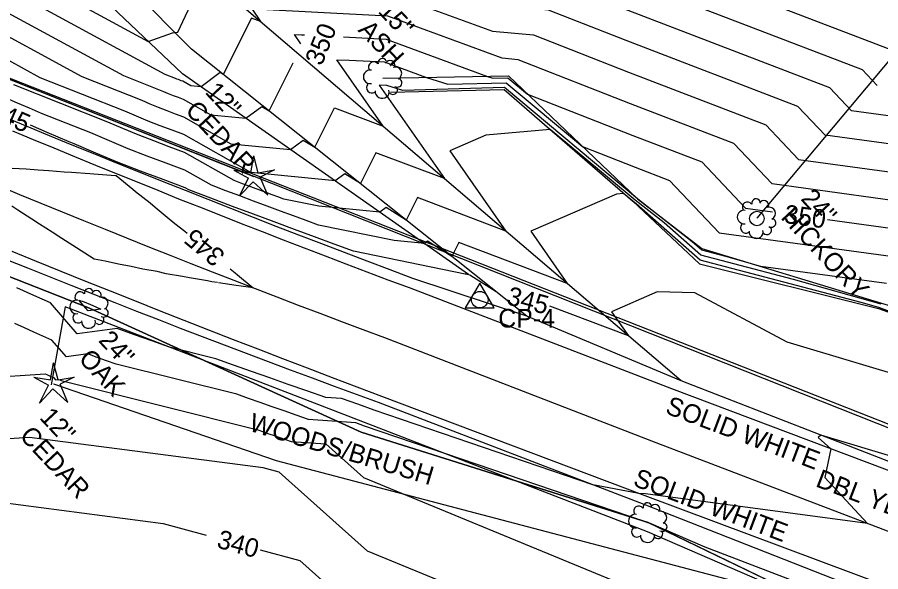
# Model space of a CAD drawing. Extents: x 487096 to 489566, y 221939 to 224454.
# Drawn here: x 487821.4 to 487970.1, y 223738.9 to 223834.5 of the extents above; entities that cross this region are included whole.
import ezdxf

# ---------------------------------------------------------------- set-up
doc = ezdxf.new("R2010")
doc.units = 0
for name, color, linetype in [('SV_BKLN_BKLN', 7, 'Continuous'), ('SV_BKLN_EARTH_TOP', 7, 'Continuous'), ('SV_CTRL_BM', 7, 'Continuous'), ('SV_CTRL_BM_INFO_BOX', 7, 'Continuous'), ('SV_CTRL_CPT', 7, 'Continuous'), ('SV_FENC_FENCES', 7, 'Continuous'), ('SV_MISC_MISC_TOPO', 7, 'Continuous'), ('SV_PIPE_RC_TX', 7, 'Continuous'), ('SV_ROAD_BITRD', 7, 'Continuous'), ('SV_ROAD_GRAVRD', 7, 'Continuous'), ('SV_ROWL_HWYLOC', 7, 'Continuous'), ('SV_SURF_INDEX_CONTOUR', 7, 'Continuous'), ('SV_SURF_INTER_CONTOUR', 7, 'Continuous'), ('SV_TRAF_PVMTL', 7, 'Continuous'), ('SV_TRAF_TRAF_TX', 7, 'Continuous'), ('SV_TREE_TREELN', 7, 'Continuous'), ('SV_TREE_TREEVEG', 7, 'Continuous'), ('SV_TREE_TREEVEG_TX', 7, 'Continuous'), ('SV_UTOH_OVERHEAD_LINES', 7, 'Continuous'), ('SV_WALL_STONE_WALL', 7, 'Continuous')]:
    doc.layers.add(name, color=color, linetype=linetype)

msp = doc.modelspace()

# ---------------------------------------------------------------- linework, layer by layer
at = {"layer": 'SV_BKLN_BKLN'}
msp.add_lwpolyline([(487885.7, 223821.61), (487905.24, 223822.04), (487927.4, 223802.77), (487938.91, 223792), (487969.73, 223784.31), (487995.3, 223775.15), (488005.95, 223768.55)], dxfattribs=at)
at = {"layer": 'SV_BKLN_EARTH_TOP'}
msp.add_lwpolyline([(487899.13, 223790.17), (487849.86, 223824.73), (487785.15, 223886.13)], dxfattribs=at)
at = {"layer": 'SV_CTRL_BM'}
msp.add_line((487948.79, 223799.81), (487948.79, 223799.81), dxfattribs=at)
msp.add_circle((487948.79, 223799.81), 1.25, dxfattribs=at)
at = {"layer": 'SV_CTRL_BM_INFO_BOX'}
msp.add_line((488027.75, 223894.06), (487948.76, 223799.86), dxfattribs=at)
at = {"layer": 'SV_CTRL_CPT'}
for p, q in [((487901.05, 223788.69), (487898.57, 223784.39)), ((487903.54, 223784.39), (487901.05, 223788.69)), ((487901.05, 223785.82), (487901.05, 223785.82)), ((487898.57, 223784.39), (487903.54, 223784.39))]:
    msp.add_line(p, q, dxfattribs=at)
msp.add_circle((487901.05, 223785.82), 1.43, dxfattribs=at)
at = {"layer": 'SV_FENC_FENCES'}
for points in [[(487756.92, 223854.03), (487819.74, 223823.93), (487862.12, 223807.03)], [(488168.14, 223658.69), (488156.25, 223662.12), (488127.21, 223671.39), (488093.65, 223683.37), (488020.23, 223704.76), (487973.09, 223726.63), (487930.05, 223747.42), (487880.61, 223763.01), (487833.81, 223784.33), (487750.08, 223817.31)]]:
    msp.add_lwpolyline(points, dxfattribs=at)
at = {"layer": 'SV_MISC_MISC_TOPO'}
for p, q in [((487901.03, 223785.78), (487901.03, 223785.78)), ((487901.07, 223785.81), (487901.07, 223785.81))]:
    msp.add_line(p, q, dxfattribs=at)
at = {"layer": 'SV_ROAD_BITRD'}
for points in [[(487991.62, 223750.14), (487935.77, 223771.81), (487909.17, 223782.99), (487889.55, 223789.46), (487885.61, 223790.94), (487881.68, 223792.43), (487877.76, 223793.93), (487873.83, 223795.43), (487869.91, 223796.94), (487865.99, 223798.46), (487862.08, 223799.99), (487858.16, 223801.52), (487854.25, 223803.06), (487850.35, 223804.61), (487846.44, 223806.17), (487842.54, 223807.73), (487838.64, 223809.3), (487834.75, 223810.88), (487830.86, 223812.47), (487826.97, 223814.06), (487823.08, 223815.66), (487819.2, 223817.27)], [(487982.7, 223729.58), (487929.37, 223750.5), (487883.63, 223768.08), (487879.84, 223769.47), (487876.04, 223770.87), (487872.25, 223772.28), (487868.46, 223773.7), (487864.67, 223775.12), (487860.88, 223776.55), (487857.1, 223777.99), (487853.32, 223779.43), (487849.54, 223780.88), (487845.77, 223782.34), (487842, 223783.81), (487838.23, 223785.28), (487834.47, 223786.77), (487830.7, 223788.26), (487826.94, 223789.75), (487823.19, 223791.26), (487819.44, 223792.77)]]:
    msp.add_lwpolyline(points, dxfattribs=at)
at = {"layer": 'SV_ROAD_GRAVRD'}
for points in [[(487935.77, 223771.81), (487858.55, 223837.83), (487796.63, 223896.51)], [(487909.17, 223782.99), (487851.39, 223829), (487789.82, 223890.99)]]:
    msp.add_lwpolyline(points, dxfattribs=at)
at = {"layer": 'SV_ROWL_HWYLOC'}
for points in [[(487756.92, 223854.03), (487819.74, 223823.93), (487982.51, 223759.36), (488009.69, 223754.74), (488041.14, 223750.63), (488071.96, 223735.45), (488100.92, 223722.74), (488124.66, 223715.6), (488155.68, 223709.25), (488178.9, 223706.07), (488296.16, 223658.56), (488379.4, 223617.17), (488410.15, 223595.68), (488443.8, 223549.21), (488472.24, 223469.86), (488477.06, 223418.16), (488475.62, 223352.08), (488474.08, 223317.48), (488463.17, 223231.25), (488461.58, 223189.46)], [(487750.08, 223817.31), (487833.81, 223784.33), (487880.61, 223763.01), (487930.05, 223747.42), (487951.57, 223737.03), (487996.66, 223715.69), (488020.23, 223704.76), (488056.94, 223694.06), (488093.65, 223683.37), (488127.21, 223671.39), (488156.25, 223662.12), (488168.14, 223658.69), (488264.6, 223621.9)]]:
    msp.add_lwpolyline(points, dxfattribs=at)
at = {"layer": 'SV_SURF_INDEX_CONTOUR'}
for points in [[(487888.61, 223849.63), (487898.24, 223846.09), (487918.12, 223844.3), (487925.47, 223841.41), (487966.91, 223825.5), (487969.53, 223822.73)], [(487802.49, 223843.56), (487810.68, 223840.22), (487839.71, 223824.46), (487845.74, 223822.07), (487846.58, 223821.71), (487847.41, 223821.36), (487848.27, 223821.03), (487849.12, 223820.71), (487849.97, 223820.4), (487854.74, 223817.68), (487860.74, 223817.09), (487863.51, 223819.14), (487864.76, 223818.36), (487868.89, 223826.63), (487868.91, 223826.62)], [(487870.24, 223829.93), (487869.13, 223831.51), (487870.37, 223831.49), (487870.85, 223831.46)], [(487877.61, 223831.11), (487884.92, 223830.72), (487902.37, 223824.31), (487903.31, 223824.01), (487905.9, 223824.08), (487909.28, 223821.25), (487927.44, 223814.12), (487939.28, 223809.57), (487946.85, 223801.57), (487951.46, 223800.94)], [(487903.86, 223787.18), (487899.33, 223790.03), (487898.86, 223790.15), (487898.72, 223790.19), (487898.57, 223790.24), (487879.32, 223794.2), (487876, 223795.4), (487872.61, 223796.64), (487869.17, 223797.91), (487865.66, 223799.21), (487862.08, 223800.54), (487858.44, 223801.9), (487854.72, 223803.3), (487850.94, 223804.73), (487850.33, 223805.07), (487846.51, 223806.51), (487842.64, 223807.97), (487838.75, 223809.45), (487834.95, 223811.06), (487831.18, 223812.67), (487830.33, 223813.01), (487826.55, 223814.63), (487823.67, 223815.87)], [(487820.51, 223808.51), (487822.95, 223808.35), (487825.02, 223808.19), (487826.86, 223808.07), (487829.48, 223807.87), (487830.75, 223807.79), (487833.91, 223807.54), (487834.6, 223807.5), (487838.29, 223807.21), (487838.43, 223807.2), (487841.29, 223804.89), (487841.78, 223804.49), (487844.26, 223802.49), (487845.15, 223801.74), (487847.24, 223800.06), (487848.55, 223798.97), (487850.24, 223797.61), (487850.64, 223797.28)], [(487855.91, 223788.77), (487854.92, 223788.92), (487854.16, 223789.08), (487851.04, 223789.58), (487849.87, 223789.83), (487847.06, 223790.3), (487845.49, 223790.65), (487843, 223791.09), (487841.04, 223791.54), (487838.86, 223791.93), (487836.52, 223792.48), (487834.65, 223792.83), (487833.05, 223793.84), (487830.99, 223795.18), (487829.1, 223796.38), (487827.4, 223797.47), (487825.24, 223798.84), (487823.9, 223799.71), (487821.48, 223801.25), (487820.47, 223801.91)], [(487960.97, 223799.64), (487973.47, 223797.92), (487993.5, 223788.25), (488003.67, 223781.54), (488008.98, 223772.72), (488010.27, 223767.56), (488011.98, 223766.57), (488014.18, 223764.36), (488018.27, 223753.62), (488024.42, 223749.97)], [(487858.04, 223791.16), (487858.91, 223790.43), (487859.31, 223790.11), (487862.01, 223787.86), (487858.72, 223788.32), (487858.36, 223788.4), (487856.04, 223788.75)], [(487985.01, 223766), (487976.08, 223771.92), (487953.99, 223778.52), (487938.13, 223786.98), (487931.62, 223787.16), (487923.76, 223783.75), (487926.67, 223779.59), (487913.14, 223784.71)], [(487771.75, 223766.41), (487802.26, 223752.04), (487803.55, 223751.39), (487804.83, 223750.74), (487806.1, 223750.11), (487818.48, 223750.92), (487846.53, 223747.27), (487853.95, 223745.24)], [(487863.21, 223742.72), (487870.05, 223740.85), (487882.45, 223729.81), (487911.79, 223717.73), (487942.75, 223718.2)]]:
    msp.add_lwpolyline(points, dxfattribs=at)
msp.add_lwpolyline([(487832.93, 223785.44), (487833.99, 223784.98), (487834.94, 223784.57), (487835.81, 223784.2), (487833.61, 223783.91), (487832.01, 223785.75)], close=True, dxfattribs=at)
at = {"layer": 'SV_SURF_INTER_CONTOUR'}
for points in [[(487765.48, 223905.98), (487780.53, 223880.87), (487783.45, 223879.37), (487783.98, 223879.12), (487784.51, 223878.88), (487785.05, 223878.63), (487788.44, 223876.46), (487791.14, 223875.36), (487803.66, 223868.56), (487804.97, 223869.03), (487810.87, 223869.79), (487817.84, 223870.37), (487819.79, 223874.57), (487850.2, 223858.52), (487872.81, 223855.08), (487886.78, 223854.35), (487896.57, 223850.75), (487920.73, 223848.58), (487925.08, 223846.87), (487972.43, 223828.69)], [(487978.17, 223816.6), (487965.1, 223818.39), (487961.38, 223822.32), (487925.87, 223835.95), (487915.52, 223840.02), (487899.91, 223841.42), (487886.16, 223846.48), (487866.54, 223847.5), (487853.87, 223849.43), (487836.82, 223858.42), (487833.44, 223851.14), (487829.71, 223850.83), (487826.55, 223850.42), (487823.81, 223849.45), (487797.65, 223863.65), (487792.03, 223865.94), (487784.93, 223870.47), (487783.82, 223870.99), (487782.71, 223871.5), (487781.61, 223872.02), (487775.5, 223875.15), (487763.66, 223894.91)], [(487976.99, 223811.93), (487960.54, 223814.18), (487955.86, 223819.13), (487926.26, 223830.49), (487912.91, 223835.74), (487901.57, 223836.76), (487885.85, 223842.54), (487863.41, 223843.71), (487855.7, 223844.89), (487845.34, 223850.35), (487841.23, 223841.53), (487839.12, 223841.35), (487837.34, 223841.12), (487833.88, 223839.89), (487800.91, 223857.79), (487793.82, 223860.68), (487784.87, 223866.39), (487783.47, 223867.04), (487782.07, 223867.69), (487780.68, 223868.34), (487772.98, 223872.29), (487762.74, 223889.37)], [(487761.83, 223883.84), (487770.46, 223869.43), (487779.76, 223864.67), (487781.44, 223863.88), (487783.12, 223863.1), (487784.82, 223862.31), (487795.61, 223855.42), (487804.16, 223851.94), (487843.95, 223830.33), (487848.13, 223831.82), (487848.54, 223831.87), (487849.03, 223831.91), (487853.85, 223842.28), (487857.54, 223840.34), (487860.28, 223839.92), (487885.54, 223838.6), (487903.24, 223832.09), (487910.31, 223831.46), (487926.65, 223825.04), (487950.33, 223815.94), (487955.98, 223809.98), (487975.82, 223807.26)], [(487974.64, 223802.59), (487951.42, 223805.78), (487944.81, 223812.76), (487927.04, 223819.58), (487907.7, 223827.17), (487904.91, 223827.42), (487885.23, 223834.66), (487862.21, 223835.87), (487861.83, 223835.88), (487863.29, 223833.78), (487861.75, 223834.36), (487856.88, 223824.63), (487856.37, 223824.95), (487853.05, 223822.49), (487851.29, 223822.67), (487849.89, 223823.46), (487849.65, 223823.55), (487849.4, 223823.65), (487849.15, 223823.74), (487848.9, 223823.85), (487848.66, 223823.95), (487846.89, 223824.65), (487807.42, 223846.08)], [(487813.93, 223834.37), (487832.53, 223824.27), (487842.83, 223820.19), (487844.25, 223819.58), (487845.68, 223818.98), (487847.15, 223818.42), (487848.6, 223817.87), (487850.04, 223817.33), (487858.2, 223812.7), (487868.44, 223811.7), (487870.65, 223813.33), (487872.63, 223812.09), (487876.03, 223818.89), (487884.41, 223815.72), (487876.43, 223827.15), (487878.54, 223827.1), (487884.61, 223826.79), (487891.89, 223824.11), (487895.55, 223822.95), (487905.62, 223823.22), (487918.74, 223812.23), (487927.83, 223808.66), (487933.76, 223806.38), (487942.29, 223797.37), (487972.29, 223793.26)], [(487971.12, 223788.59), (487949.48, 223791.55), (487943.42, 223793.25), (487939.28, 223794.33), (487937.64, 223795.79), (487928.27, 223803.16), (487928.23, 223803.2), (487928.21, 223803.2), (487905.34, 223822.36), (487887.79, 223821.89), (487885.06, 223822.76), (487883.74, 223822.78), (487894.98, 223806.69), (487883.18, 223811.15), (487880.51, 223805.82), (487877.79, 223807.52), (487876.14, 223806.3), (487861.65, 223807.72), (487850.11, 223814.27), (487848.08, 223815.03), (487846.02, 223815.81), (487843.95, 223816.59), (487841.92, 223817.45), (487839.92, 223818.31), (487825.35, 223824.08), (487817.19, 223828.51)], [(487970.17, 223785.07), (487955.08, 223789.29), (487939.14, 223793.48), (487932.82, 223799.07), (487927.84, 223802.99), (487913.18, 223815.13), (487902.13, 223814.18), (487895.89, 223811.47), (487905.54, 223797.65), (487890.32, 223803.42), (487888.38, 223799.55), (487884.94, 223801.71), (487883.83, 223800.9), (487873.33, 223801.93), (487867.31, 223803.16), (487866.3, 223803.53), (487865.28, 223803.9), (487864.25, 223804.28), (487863.19, 223804.67), (487862.11, 223805.08), (487861.01, 223805.49), (487859.89, 223805.91), (487858.75, 223806.34), (487850.19, 223811.2), (487847.55, 223812.19), (487844.89, 223813.19), (487842.21, 223814.21), (487839.6, 223815.32), (487837, 223816.43), (487820.78, 223822.86)], [(487978.99, 223781), (487969.82, 223784.47), (487966.75, 223785.33), (487939.01, 223792.62), (487928, 223802.36), (487927.45, 223802.79), (487925.83, 223804.14), (487924.6, 223804.03), (487909.83, 223797.61), (487916.1, 223788.62), (487897.46, 223795.68), (487896.26, 223793.28), (487892.08, 223795.9), (487891.53, 223795.5), (487886.31, 223796.01), (487873.31, 223798.68), (487871.15, 223799.47), (487868.95, 223800.27), (487866.71, 223801.1), (487864.42, 223801.94), (487862.09, 223802.81), (487859.72, 223803.69), (487857.31, 223804.6), (487854.84, 223805.54), (487850.26, 223808.14), (487847.03, 223809.35), (487843.77, 223810.58), (487840.48, 223811.83), (487837.27, 223813.19), (487834.09, 223814.55), (487825.55, 223817.93), (487823.48, 223818.82), (487821.45, 223819.7), (487819.46, 223820.56)], [(487974.88, 223715.46), (487963.2, 223719.55), (487951.33, 223726.23), (487942.64, 223727.98), (487917.87, 223727.61), (487881.75, 223742.48), (487866.49, 223756.07), (487863.73, 223756.82), (487823.49, 223762.06), (487805.74, 223760.9), (487803.91, 223761.8), (487802.08, 223762.72), (487800.23, 223763.66), (487763.32, 223781.04), (487761.36, 223782.04), (487759.38, 223783.05), (487757.39, 223784.08), (487755.39, 223785.11), (487753.37, 223786.16), (487751.34, 223787.22), (487732, 223805.45), (487731.77, 223805.56), (487730.56, 223805.74)], [(487987.72, 223754.08), (487959.79, 223762.49), (487959.36, 223762.08), (487961.53, 223760.14), (487960.51, 223755.17), (487967.86, 223747.24), (487929.63, 223752.36), (487928.43, 223752.41), (487928.19, 223752.46), (487920.51, 223753.91), (487882.87, 223766.8), (487880.04, 223767.79), (487877.26, 223768.77), (487874.54, 223768.96), (487871.29, 223770.09), (487868.07, 223771.22), (487864.89, 223772.33), (487861.74, 223773.44), (487858.64, 223774.55), (487855.57, 223775.65), (487847.63, 223777.63), (487844.58, 223778.71), (487841.56, 223779.79), (487838.6, 223780.85), (487831.73, 223779.94), (487827.12, 223785.25), (487824.25, 223786.54), (487821.32, 223787.87)], [(487967.61, 223732.53), (487939.9, 223743.16), (487930.16, 223747.36), (487930.08, 223747.37), (487930.02, 223747.37), (487929.43, 223747.61), (487895.22, 223759.26), (487881.23, 223764.05), (487880.45, 223764.32), (487879.69, 223764.59), (487871.57, 223765.17), (487869.45, 223765.9), (487867.35, 223766.64), (487865.28, 223767.36), (487863.23, 223768.09), (487861.21, 223768.81), (487859.21, 223769.52), (487838.42, 223774.72), (487836.77, 223775.31), (487835.15, 223775.88), (487833.55, 223776.46), (487829.85, 223775.96), (487827.37, 223778.83), (487825.82, 223779.52), (487824.24, 223780.24), (487822.63, 223780.97), (487820.99, 223781.72)], [(487805.37, 223771.68), (487826.22, 223773.04), (487826.46, 223772.93), (487826.7, 223772.82), (487826.94, 223772.71), (487827.17, 223772.61), (487827.4, 223772.5), (487827.62, 223772.4), (487827.97, 223771.99), (487828.5, 223772.06), (487828.73, 223771.98), (487828.97, 223771.9), (487829.2, 223771.82), (487862.85, 223763.4), (487863.78, 223763.06), (487864.72, 223762.73), (487865.67, 223762.39), (487866.63, 223762.06), (487867.61, 223761.72), (487868.59, 223761.37), (487874.52, 223760.95), (487881.05, 223755.15), (487923.94, 223737.49)]]:
    msp.add_lwpolyline(points, dxfattribs=at)
at = {"layer": 'SV_TRAF_PVMTL'}
for points in [[(487991.38, 223748.88), (487934.13, 223770.48), (487888.93, 223787.84), (487885.3, 223789.2), (487881.69, 223790.56), (487878.07, 223791.93), (487874.46, 223793.31), (487870.85, 223794.7), (487867.24, 223796.09), (487863.64, 223797.49), (487860.04, 223798.9), (487856.44, 223800.32), (487852.84, 223801.74), (487849.25, 223803.17), (487845.66, 223804.61), (487842.08, 223806.05), (487838.49, 223807.51), (487834.91, 223808.97), (487831.34, 223810.43), (487827.76, 223811.91), (487824.19, 223813.39), (487820.62, 223814.88)], [(487986.33, 223740.18), (487931.44, 223761.15), (487884.72, 223779.22), (487881, 223780.62), (487877.28, 223782.02), (487873.57, 223783.42), (487869.85, 223784.84), (487866.14, 223786.26), (487862.44, 223787.69), (487858.73, 223789.13), (487855.03, 223790.57), (487851.33, 223792.02), (487847.64, 223793.48), (487843.94, 223794.95), (487840.25, 223796.42), (487836.57, 223797.9), (487832.88, 223799.39), (487829.2, 223800.89), (487825.52, 223802.39), (487821.85, 223803.9), (487818.18, 223805.42)], [(487983.46, 223731.85), (487929.55, 223751.99), (487884.2, 223769.15), (487879.93, 223770.76), (487875.67, 223772.38), (487871.41, 223774.01), (487867.15, 223775.64), (487862.9, 223777.28), (487858.64, 223778.93), (487854.4, 223780.59), (487850.15, 223782.25), (487845.91, 223783.92), (487841.67, 223785.6), (487837.43, 223787.29), (487833.19, 223788.98), (487828.96, 223790.68), (487824.73, 223792.39), (487820.51, 223794.11)]]:
    msp.add_lwpolyline(points, dxfattribs=at)
at = {"layer": 'SV_TREE_TREELN'}
msp.add_lwpolyline([(487827.66, 223771.33), (487866.01, 223758.08), (487950.26, 223735.93)], dxfattribs=at)
at = {"layer": 'SV_TREE_TREEVEG'}
for p, q in [((487884.38, 223823.97), (487884.38, 223823.97)), ((487861.6, 223807.7), (487862.12, 223810.61)), ((487862.89, 223807.71), (487862.12, 223810.61)), ((487858.72, 223808.14), (487861.23, 223806.77)), ((487858.72, 223808.14), (487861.6, 223807.7)), ((487862.89, 223807.71), (487865.68, 223808.19)), ((487865.68, 223808.19), (487863.23, 223806.95)), ((487859.69, 223803.69), (487861.23, 223806.77)), ((487862, 223806.14), (487859.69, 223803.69)), ((487862, 223806.14), (487864.56, 223803.82)), ((487862.12, 223807.03), (487862.12, 223807.03)), ((487864.56, 223803.82), (487863.23, 223806.95)), ((487948.79, 223799.81), (487948.79, 223799.81)), ((487833.81, 223784.33), (487833.81, 223784.33)), ((487827.14, 223772), (487827.66, 223774.91)), ((487828.42, 223772), (487827.66, 223774.91)), ((487824.26, 223772.44), (487826.77, 223771.07)), ((487824.26, 223772.44), (487827.14, 223772)), ((487828.42, 223772), (487831.22, 223772.49)), ((487831.22, 223772.49), (487828.76, 223771.25)), ((487825.23, 223767.98), (487826.77, 223771.07)), ((487827.54, 223770.43), (487825.23, 223767.98)), ((487827.54, 223770.43), (487830.09, 223768.11)), ((487827.66, 223771.33), (487827.66, 223771.33)), ((487830.09, 223768.11), (487828.76, 223771.25)), ((487930.05, 223747.42), (487930.05, 223747.42))]:
    msp.add_line(p, q, dxfattribs=at)
msp.add_lwpolyline([(488167.81, 223598.31), (488191.14, 223648.28), (488087.41, 223684.16), (488015.83, 223708.57), (487929.95, 223745.8), (487829.66, 223784.61), (487827.21, 223771.15)], dxfattribs=at)
for centre, radius, start, end in [((487882.77, 223825.93), 0.874, 35.9933, 211.459), ((487884.27, 223826.62), 0.75, 23.2911, 192.3579), ((487885.59, 223826.2), 0.85, 345.5308, 152.7093), ((487882.18, 223824.21), 1.17, 79.3292, 279.9889), ((487886.55, 223824.85), 1.06, 294.1859, 111.1082), ((487882.47, 223822.36), 0.922, 137.0157, 304.5501), ((487948.67, 223802.46), 0.75, 23.2911, 192.3579), ((487947.17, 223801.78), 0.874, 35.9933, 211.459), ((487949.99, 223802.05), 0.85, 345.5308, 152.7093), ((487950.95, 223800.69), 1.06, 294.1859, 111.1082), ((487946.58, 223800.06), 1.17, 79.3292, 279.9889), ((487946.87, 223798.21), 0.922, 137.0157, 304.5501), ((487832.2, 223786.29), 0.874, 35.9933, 211.459), ((487833.7, 223786.98), 0.75, 23.2911, 192.3579), ((487835.01, 223786.56), 0.85, 345.5308, 152.7093), ((487831.61, 223784.57), 1.17, 79.3292, 279.9889), ((487835.97, 223785.21), 1.06, 294.1859, 111.1082), ((487831.89, 223782.72), 0.922, 137.0157, 304.5501), ((487928.44, 223749.38), 0.874, 35.9933, 211.459), ((487929.94, 223750.07), 0.75, 23.2911, 192.3579), ((487931.25, 223749.66), 0.85, 345.5308, 152.7093), ((487927.85, 223747.67), 1.17, 79.3292, 279.9889), ((487932.21, 223748.3), 1.06, 294.1859, 111.1082), ((487928.13, 223745.82), 0.922, 137.0157, 304.5501)]:
    msp.add_arc(centre, radius, start, end, dxfattribs=at)
for centre, major_axis, ratio, start_param, end_param in [((487886.84, 223823.2), (0.822, -0.013), 0.901056, 4.216583, 7.444153), ((487886.1, 223822), (0.08, -0.798), 0.999752, 5.391582, 8.241319), ((487884.26, 223821.63), (-1.2, 0.16), 0.902156, 0, 3.5401), ((487951.24, 223799.05), (0.822, -0.013), 0.901056, 4.216583, 7.444153), ((487948.66, 223797.48), (-1.2, 0.16), 0.902156, 0, 3.5401), ((487950.5, 223797.84), (0.08, -0.798), 0.999752, 5.391582, 8.241319), ((487836.26, 223783.56), (0.822, -0.013), 0.901056, 4.216583, 7.444153), ((487833.68, 223781.99), (-1.2, 0.16), 0.902156, 0, 3.5401), ((487835.53, 223782.36), (0.08, -0.798), 0.999752, 5.391582, 8.241319), ((487932.5, 223746.65), (0.822, -0.013), 0.901056, 4.216583, 7.444153), ((487929.92, 223745.08), (-1.2, 0.16), 0.902156, 0, 3.5401), ((487931.77, 223745.45), (0.08, -0.798), 0.999752, 5.391582, 8.241319)]:
    msp.add_ellipse(centre, major_axis=major_axis, ratio=ratio, start_param=start_param, end_param=end_param, dxfattribs=at)
at = {"layer": 'SV_UTOH_OVERHEAD_LINES'}
msp.add_lwpolyline([(488477.01, 222631.44), (488424.13, 222778.25), (488391.68, 223012.96), (488449.87, 223205.72), (488470, 223438.33), (488349.56, 223622.89), (488159.18, 223693.12), (487993.17, 223755.78), (487804.2, 223830.22), (487742.26, 223860.21)], dxfattribs=at)
at = {"layer": 'SV_WALL_STONE_WALL'}
msp.add_lwpolyline([(487884.38, 223823.97), (487906, 223824.38), (487928.22, 223803.19), (487939.33, 223794.64), (487970.27, 223785.24), (487995.99, 223777.6), (488005.6, 223769.42), (488016.25, 223765.18), (488051.84, 223755.29), (488077.81, 223742.44), (488110.99, 223740.41), (488131.68, 223731.12)], dxfattribs=at)

# ---------------------------------------------------------------- texts
at = {"layer": 'SV_PIPE_RC_TX'}
msp.add_text('CP-4', height=3.2, dxfattribs=at).set_placement((487904.25, 223781.02))
at = {"layer": 'SV_SURF_INDEX_CONTOUR'}
for s, rotation, p in [('350', 68.1003, (487873.82, 223825.98)), ('345', 336.5471, (487816.2, 223817.37)), ('350', 352.1985, (487953.37, 223799.06)), ('345', 140.4286, (487857.4, 223793.76)), ('345', 345.203, (487905.52, 223785.07)), ('340', 344.7284, (487855.6, 223743.14))]:
    msp.add_text(s, height=3.2, rotation=rotation, dxfattribs=at).set_placement(p)
at = {"layer": 'SV_TRAF_TRAF_TX'}
for s, rotation, p in [('SOLID WHITE', 339.3252, (487932.83, 223766.29)), ('SOLID WHITE', 339.3252, (487927.29, 223753.83)), ('DBL YELLOW', 339.0964, (487958.74, 223753.69))]:
    msp.add_text(s, height=3.2, rotation=rotation, dxfattribs=at).set_placement(p)
at = {"layer": 'SV_TREE_TREEVEG_TX'}
for s, rotation, p in [('15"', 313.0386, (487883.39, 223835.4)), ('ASH', 313.0386, (487879.96, 223832.19)), ('12"', 313.0386, (487853.6, 223821.5)), ('CEDAR', 313.0386, (487850.17, 223818.29)), ('24"', 313.0386, (487956.2, 223803.11)), ('HICKORY', 313.0386, (487952.76, 223799.9)), ('24"', 313.0386, (487835.24, 223778.69)), ('OAK', 313.0386, (487831.8, 223775.48)), ('12"', 313.0386, (487825.07, 223765.42)), ('WOODS/BRUSH', 343.2564, (487861.12, 223763.28)), ('CEDAR', 313.0386, (487821.64, 223762.21))]:
    msp.add_text(s, height=3.2, rotation=rotation, dxfattribs=at).set_placement(p)

doc.saveas('drawing.dxf')
